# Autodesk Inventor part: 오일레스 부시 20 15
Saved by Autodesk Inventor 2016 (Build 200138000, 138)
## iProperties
Created: 2024-08
Part Number: 오일레스 부시 20 15
Material: 일반
Document SubType Name: Modeling
Designer: pc-2
Density: 1 g/cm^3
Appearance: 기본값
Author: jhkim
Sending System: Autodesk Inventor 2025
Preprocessor: ST-DEVELOPER v20
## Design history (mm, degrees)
node "오일레스 부시 20 151"
node "솔리드2"
node "솔리드1"
